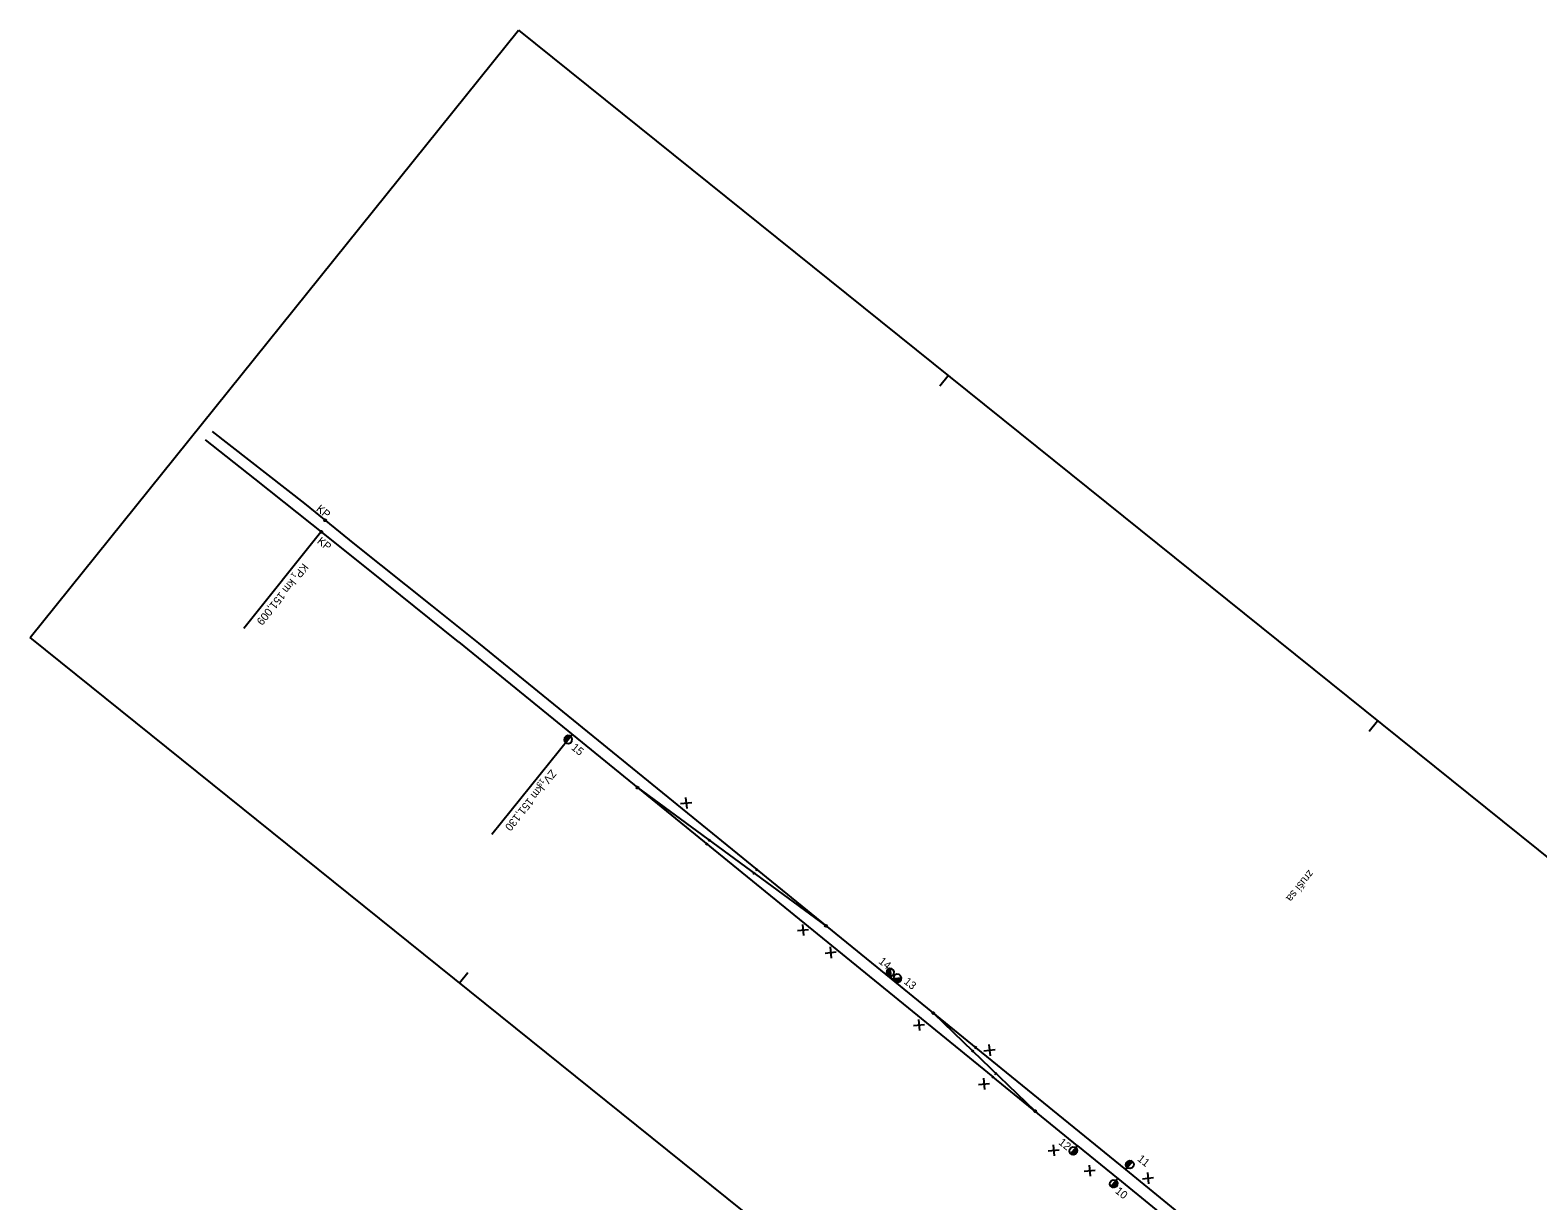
# Model space of a CAD drawing. Extents: x -491586 to -489736, y -1309039 to -1307479.
# Drawn here: x -491586 to -491011, y -1307925 to -1307479 of the extents above; entities that cross this region are included whole.
import ezdxf

# ---------------------------------------------------------------- set-up
doc = ezdxf.new("R2010")
doc.units = 0
for name, color, linetype in [('Level 1', 7, 'Continuous'), ('Level 11', 7, 'Continuous'), ('Level 6', 7, 'Continuous'), ('Level 61', 7, 'Continuous')]:
    doc.layers.add(name, color=color, linetype=linetype)

msp = doc.modelspace()

# ---------------------------------------------------------------- linework, layer by layer
at = {"layer": 'Level 1'}
for p, q in [((-491516.47, -1307631.95), (-491481.38, -1307659.33)), ((-491500.27, -1307650.01), (-491519.04, -1307635.16)), ((-491472.97, -1307671.71), (-491500.27, -1307650.01)), ((-491481.38, -1307659.33), (-491462.33, -1307674.87)), ((-491450.55, -1307689.61), (-491472.97, -1307671.71)), ((-491462.33, -1307674.87), (-491432.84, -1307698.37)), ((-491422.62, -1307712.12), (-491450.55, -1307689.61)), ((-491432.84, -1307698.37), (-491415.03, -1307712.64)), ((-491422.62, -1307712.12), (-491219.03, -1307877.87)), ((-491415.03, -1307712.64), (-491257.83, -1307840.52)), ((-491354.44, -1307767.63), (-491354.44, -1307767.63)), ((-491354.44, -1307767.63), (-491282.67, -1307820.31)), ((-491328.4, -1307789.47), (-491327.76, -1307788.7)), ((-491328.08, -1307789.09), (-491328.08, -1307789.09)), ((-491327.37, -1307788.1), (-491326.73, -1307787.32)), ((-491327.05, -1307787.71), (-491327.05, -1307787.71)), ((-491310.41, -1307800.6), (-491309.77, -1307799.82)), ((-491310.09, -1307800.21), (-491310.09, -1307800.21)), ((-491309.38, -1307799.23), (-491308.75, -1307798.46)), ((-491309.07, -1307798.85), (-491309.07, -1307798.85)), ((-491282.67, -1307820.31), (-491282.67, -1307820.31)), ((-491257.83, -1307840.52), (-491225.56, -1307866.77)), ((-491241.69, -1307853.65), (-491241.69, -1307853.65)), ((-491241.69, -1307853.65), (-491226.71, -1307868.06)), ((-491226.36, -1307867.7), (-491227.05, -1307868.42)), ((-491202.9, -1307891), (-491226.71, -1307868.06)), ((-491226.71, -1307868.06), (-491226.71, -1307868.06)), ((-491225.25, -1307866.38), (-491225.88, -1307867.16)), ((-491225.56, -1307866.77), (-491225.56, -1307866.77)), ((-491225.56, -1307866.77), (-491168.41, -1307913.26)), ((-491219.34, -1307878.26), (-491218.71, -1307877.49)), ((-491186.77, -1307904.14), (-491219.03, -1307877.87)), ((-491219.03, -1307877.87), (-491219.03, -1307877.87)), ((-491218.23, -1307876.94), (-491217.53, -1307876.22)), ((-491217.88, -1307876.58), (-491217.88, -1307876.58)), ((-491202.9, -1307891), (-491202.9, -1307891)), ((-491186.77, -1307904.14), (-491171.26, -1307916.77)), ((-491168.41, -1307913.26), (-491136.15, -1307939.51)), ((-491171.4, -1307916.65), (-491139.14, -1307942.89))]:
    msp.add_line(p, q, dxfattribs=at)
for points in [[(-491354.2, -1307767.31), (-491354.04, -1307767.67), (-491354.28, -1307767.99), (-491354.68, -1307767.95), (-491354.84, -1307767.58), (-491354.6, -1307767.26), (-491354.2, -1307767.31)], [(-491282.43, -1307819.99), (-491282.27, -1307820.36), (-491282.51, -1307820.68), (-491282.91, -1307820.63), (-491283.07, -1307820.26), (-491282.83, -1307819.94), (-491282.43, -1307819.99)], [(-491241.38, -1307853.9), (-491241.76, -1307854.04), (-491242.07, -1307853.79), (-491242, -1307853.39), (-491241.63, -1307853.25), (-491241.32, -1307853.5), (-491241.38, -1307853.9)], [(-491203.21, -1307890.75), (-491202.84, -1307890.61), (-491202.53, -1307890.86), (-491202.59, -1307891.26), (-491202.96, -1307891.4), (-491203.27, -1307891.15), (-491203.21, -1307890.75)]]:
    msp.add_lwpolyline(points, dxfattribs=at)
at = {"layer": 'Level 11'}
for p, q in [((-491473.45, -1307665.76), (-491473.45, -1307665.76)), ((-491475.04, -1307670.34), (-491504.49, -1307706.96)), ((-491474.91, -1307670.18), (-491474.91, -1307670.18)), ((-491380.52, -1307748.94), (-491409.9, -1307785.47)), ((-491379.28, -1307747.41), (-491381.77, -1307750.47)), ((-491379.28, -1307747.41), (-491379.28, -1307747.41)), ((-491336.13, -1307771.38), (-491335.69, -1307775.63)), ((-491338.04, -1307773.72), (-491333.78, -1307773.28)), ((-491293.5, -1307822.13), (-491289.24, -1307821.7)), ((-491291.59, -1307819.79), (-491291.15, -1307824.04)), ((-491281.01, -1307828.39), (-491280.58, -1307832.64)), ((-491282.92, -1307830.73), (-491278.67, -1307830.3)), ((-491257.83, -1307840.52), (-491257.83, -1307840.52)), ((-491249.26, -1307858.31), (-491245.01, -1307857.88)), ((-491247.35, -1307855.97), (-491246.92, -1307860.22)), ((-491222.43, -1307867.93), (-491218.18, -1307867.5)), ((-491220.53, -1307865.59), (-491220.09, -1307869.84)), ((-491224.49, -1307880.79), (-491220.24, -1307880.36)), ((-491222.59, -1307878.45), (-491222.15, -1307882.7)), ((-491196.05, -1307903.74), (-491195.61, -1307907.99)), ((-491186.77, -1307904.14), (-491189.27, -1307907.2)), ((-491186.77, -1307904.14), (-491186.77, -1307904.14)), ((-491197.96, -1307906.08), (-491193.7, -1307905.65)), ((-491184.27, -1307913.83), (-491180.02, -1307913.4)), ((-491182.36, -1307911.49), (-491181.93, -1307915.74)), ((-491168.41, -1307913.26), (-491165.93, -1307910.18)), ((-491168.41, -1307913.26), (-491168.41, -1307913.26)), ((-491160.12, -1307914.38), (-491159.69, -1307918.64)), ((-491171.4, -1307916.65), (-491173.88, -1307919.72)), ((-491171.4, -1307916.65), (-491171.4, -1307916.65)), ((-491162.03, -1307916.73), (-491157.78, -1307916.29))]:
    msp.add_line(p, q, dxfattribs=at)
for points in [[(-491473.21, -1307665.44), (-491473.06, -1307665.8), (-491473.3, -1307666.12), (-491473.69, -1307666.08), (-491473.85, -1307665.71), (-491473.61, -1307665.39), (-491473.21, -1307665.44)], [(-491474.67, -1307669.86), (-491474.52, -1307670.23), (-491474.75, -1307670.55), (-491475.15, -1307670.5), (-491475.31, -1307670.13), (-491475.07, -1307669.81), (-491474.67, -1307669.86)], [(-491382.08, -1307750.22), (-491381.46, -1307750.72), (-491380.7, -1307750.84), (-491379.98, -1307750.57), (-491379.48, -1307749.95), (-491379.36, -1307749.19), (-491379.63, -1307748.47), (-491380.25, -1307747.97), (-491381.01, -1307747.85), (-491381.73, -1307748.12), (-491382.23, -1307748.74), (-491382.35, -1307749.5), (-491382.08, -1307750.22), (-491382.12, -1307749.86), (-491381.73, -1307750.18), (-491381.54, -1307749.95), (-491382.2, -1307749.41), (-491382.13, -1307749.08), (-491381.35, -1307749.71), (-491381.16, -1307749.48), (-491382.05, -1307748.76), (-491381.86, -1307748.52), (-491380.97, -1307749.25), (-491380.78, -1307749.02), (-491381.67, -1307748.29), (-491381.37, -1307748.15), (-491380.59, -1307748.79), (-491380.4, -1307748.55), (-491381.06, -1307748.02), (-491380.56, -1307748.04), (-491380.21, -1307748.32)], [(-491257.93, -1307839.55), (-491257.2, -1307839.28), (-491256.71, -1307838.68), (-491256.58, -1307837.91), (-491256.86, -1307837.18), (-491257.46, -1307836.69), (-491258.23, -1307836.57), (-491258.95, -1307836.84), (-491259.44, -1307837.45), (-491259.57, -1307838.21), (-491259.3, -1307838.94), (-491258.69, -1307839.43), (-491257.93, -1307839.55), (-491258.1, -1307839.2), (-491258.74, -1307839.26), (-491259.05, -1307839.01), (-491258.2, -1307838.93), (-491258.2, -1307838.61), (-491259.22, -1307838.74), (-491259.35, -1307838.44), (-491258.23, -1307838.32), (-491258.26, -1307838.04), (-491259.42, -1307838.13), (-491259.38, -1307837.84), (-491258.25, -1307837.72), (-491258.28, -1307837.44), (-491259.27, -1307837.54), (-491259.05, -1307837.2), (-491258.35, -1307837.13), (-491258.35, -1307836.81), (-491258.7, -1307836.84)], [(-491258.23, -1307836.58), (-491257.83, -1307840.52), (-491253.89, -1307840.12)], [(-491253.87, -1307840.12), (-491254.15, -1307839.39), (-491254.75, -1307838.9), (-491255.56, -1307838.79), (-491256.24, -1307839.06), (-491256.73, -1307839.66), (-491256.86, -1307840.42), (-491256.58, -1307841.15), (-491255.98, -1307841.64), (-491255.26, -1307841.77), (-491254.49, -1307841.49), (-491254, -1307840.89), (-491253.87, -1307840.12), (-491254.19, -1307840.33), (-491254.14, -1307840.82), (-491254.42, -1307841.17), (-491254.5, -1307840.4), (-491254.78, -1307840.43), (-491254.68, -1307841.41), (-491254.99, -1307841.55), (-491255.1, -1307840.42), (-491255.41, -1307840.49), (-491255.27, -1307841.58), (-491255.59, -1307841.57), (-491255.69, -1307840.52), (-491255.98, -1307840.55), (-491255.88, -1307841.53), (-491256.23, -1307841.25), (-491256.3, -1307840.55), (-491256.58, -1307840.57), (-491256.53, -1307841)], [(-491188.96, -1307907.45), (-491189.58, -1307906.94), (-491189.85, -1307906.2), (-491189.72, -1307905.46), (-491189.23, -1307904.86), (-491188.5, -1307904.58), (-491187.75, -1307904.7), (-491187.13, -1307905.2), (-491186.86, -1307905.92), (-491186.98, -1307906.68), (-491187.48, -1307907.3), (-491188.2, -1307907.57), (-491188.96, -1307907.45), (-491188.61, -1307907.41), (-491188.99, -1307907.1), (-491188.8, -1307906.87), (-491188.15, -1307907.4), (-491187.8, -1307907.3), (-491188.62, -1307906.63), (-491188.43, -1307906.4), (-491187.53, -1307907.13), (-491187.34, -1307906.9), (-491188.24, -1307906.17), (-491188.05, -1307905.94), (-491187.16, -1307906.66), (-491187.08, -1307906.34), (-491187.86, -1307905.7), (-491187.67, -1307905.47), (-491187.01, -1307906.01), (-491187.09, -1307905.55), (-491187.48, -1307905.24)], [(-491166.25, -1307909.93), (-491165.62, -1307910.43), (-491165.35, -1307911.18), (-491165.47, -1307911.92), (-491165.96, -1307912.52), (-491166.68, -1307912.81), (-491167.44, -1307912.69), (-491168.06, -1307912.19), (-491168.34, -1307911.47), (-491168.22, -1307910.72), (-491167.72, -1307910.09), (-491167.01, -1307909.82), (-491166.25, -1307909.93), (-491166.6, -1307909.97), (-491166.21, -1307910.28), (-491166.4, -1307910.52), (-491167.06, -1307909.99), (-491167.4, -1307910.09), (-491166.59, -1307910.75), (-491166.77, -1307910.99), (-491167.67, -1307910.26), (-491167.86, -1307910.5), (-491166.96, -1307911.22), (-491167.15, -1307911.45), (-491168.04, -1307910.73), (-491168.12, -1307911.06), (-491167.34, -1307911.69), (-491167.53, -1307911.92), (-491168.19, -1307911.39), (-491168.1, -1307911.84), (-491167.71, -1307912.15)], [(-491173.57, -1307919.97), (-491174.19, -1307919.47), (-491174.46, -1307918.73), (-491174.35, -1307918), (-491173.85, -1307917.37), (-491173.13, -1307917.1), (-491172.37, -1307917.21), (-491171.75, -1307917.72), (-491171.48, -1307918.43), (-491171.6, -1307919.2), (-491172.09, -1307919.8), (-491172.81, -1307920.09), (-491173.57, -1307919.97), (-491173.22, -1307919.94), (-491173.61, -1307919.62), (-491173.42, -1307919.39), (-491172.76, -1307919.92), (-491172.45, -1307919.78), (-491173.23, -1307919.16), (-491173.04, -1307918.92), (-491172.15, -1307919.64), (-491171.96, -1307919.41), (-491172.85, -1307918.69), (-491172.67, -1307918.45), (-491171.77, -1307919.18), (-491171.7, -1307918.85), (-491172.48, -1307918.22), (-491172.29, -1307917.99), (-491171.67, -1307918.49), (-491171.75, -1307918.04), (-491172.1, -1307917.75)]]:
    msp.add_lwpolyline(points, dxfattribs=at)
at = {"layer": 'Level 61'}
for p, q in [((-491585.87, -1307710.43), (-491399.74, -1307478.98)), ((-491399.75, -1307478.98), (-490908.8, -1307873.79)), ((-491239.23, -1307614.48), (-491236.1, -1307610.59)), ((-491094.92, -1308105.24), (-491585.87, -1307710.43)), ((-491075.58, -1307746.09), (-491072.45, -1307742.19)), ((-491422.22, -1307842.03), (-491419.09, -1307838.14))]:
    msp.add_line(p, q, dxfattribs=at)

# ---------------------------------------------------------------- texts
at = {"layer": 'Level 11'}
for s, height, rotation, p in [('KP', 3, 321.19445, (-491477.13, -1307661.9)), ('KP', 3, 321.19445, (-491476.77, -1307674.2)), ('KP  km 151,009', 3, 231.19445, (-491481.89, -1307681.95)), ('1', 2, 231.19445, (-491485.77, -1307685.46)), ('15', 3, 321.19445, (-491379.91, -1307752.86)), ('ZV  km 151,130', 3, 231.19445, (-491387.37, -1307760.55)), ('15', 2, 231.19445, (-491391.25, -1307764.05)), ('14', 3, 321.19445, (-491262.8, -1307834.32)), ('13', 3, 321.19445, (-491253.19, -1307842.05)), ('12', 3, 321.19445, (-491194.24, -1307903.31)), ('11', 3, 321.19445, (-491164.2, -1307909.58)), ('10', 3, 321.19445, (-491172.65, -1307921.88))]:
    msp.add_text(s, height=height, rotation=rotation, dxfattribs=at).set_placement(p)
at = {"layer": 'Level 6'}
msp.add_text('zruší sa', height=3, rotation=231.19445, dxfattribs=at).set_placement((-491098.64, -1307798.81))

doc.saveas('drawing.dxf')
